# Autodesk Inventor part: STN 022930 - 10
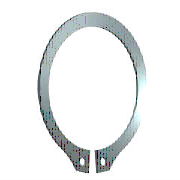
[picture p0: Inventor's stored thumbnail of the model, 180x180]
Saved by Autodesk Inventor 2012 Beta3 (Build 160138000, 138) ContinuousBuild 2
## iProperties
Created: 2010-02
Part Number: STN 022930 - 10
Material: Steel, Mild
Description: Retaining rings for shaft
Document SubType Name: Modeling
Standard: STN 022930
Designer: Thom Tremblay
Standards Organization: STN
Language: en-US
Size Designation: 10
Categories: <MemberInstance><Categories><Category DisplayName="Shaft Parts" InternalName="7f7aeb1f-a693-4053-b835-cee3144e0d98" Mnemonic="SHFT"><Category DisplayName="Circl
Density: 7.86 g/cm^3
IsCustomPart: 0
Author: Thom Tremblay
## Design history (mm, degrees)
node "WorkPlane1"
workplane "Work Plane2"
node "WorkPlane2"
node "Sketch1"
node "WorkPoint1"
node "WorkAxis1"
sketch "Sketch3"
  geometry: L1 (-0.75, -4.741)-(-0.75, -7.741) reference; L2 (-0.75, -7.741)-(-3.75, -7.212) reference; 1 further point
  dimensions: "d30" = 1.2 distance from line of L1 point (-1.95, -6.159) (= 0.8 x Diam5); "d32" = 1.35 distance from line of L2 point (-1.95, -6.159) (= 0.45 x ParA)
hole "Hole1" sketch "Sketch3" at (-1.95, -6.159) diameter "d33" = 1.5 (= Diam5); stored, may be unused: countersink angle "d37" = 60 deg, drill point angle "d39" = 118 deg; dims "d34" = 6, "d35" = 4, "d36" = 2, "d38" = 8
sketch "Sketch4"
  geometry: L1 (0.75, -7.741)-(0.75, -4.741) reference; L2 (3.75, -7.212)-(0.75, -7.741) reference; 1 further point
  dimensions: "d41" = 1.2 distance from line of L1 point (1.95, -6.159) (= 0.8 x Diam5); "d43" = 1.35 distance from line of L2 point (1.95, -6.159) (= 0.45 x ParA)
hole "Hole2" sketch "Sketch4" at (1.95, -6.159) diameter "d44" = 1.5 (= Diam5); stored, may be unused: countersink angle "d48" = 60 deg, drill point angle "d50" = 118 deg; dims "d45" = 6, "d46" = 4, "d47" = 2, "d49" = 8
fillet "Fillet1" dims "d51" = 2.25 (= 1.5 x Diam5)
body "Solid1"
sketch "Sketch2"
  geometry: L1 (3.75, -7.212)-(3.75, -4.537); L2 (0.75, -7.741)-(3.75, -7.212); L3 (0.75, -4.741)-(0.75, -7.741); L4 (-0.75, -4.741)-(-0.75, -7.741); L5 (-0.75, -7.741)-(-3.75, -7.212); L6 (-3.75, -7.212)-(-3.75, -4.537); A1 r 4.8 centre (0, 0) between (0.75, -4.741) and (-0.75, -4.741); A2 r 6.2 centre (0, 0.4) between (3.75, -4.537) and (-3.75, -4.537); 1 further point
  constraints: 12 end point, 4 point on circle, 4 vertical, 2 centre point
  dimensions: "d2" = 4.8 radius of A1 (= 0.5 x Diam2); "d4" = 6.2 radius of A2 (= 0.166667 x ParA + 0.5 x Diam2 + 0.5 x b); "d6" = 0 horizontal distance of A2.centre A1.centre; "d8" = 0.75 horizontal distance of L3.start A1.centre (= 0.5 x Diam5); "d10" = 0.75 horizontal distance of L4.start A1.centre (= 0.5 x Diam5); "d12" = 3 distance of L4.start L4.end (= ParA); "d14" = 3 distance of L3.start L2.start (= ParA); "d16" = 80 deg angle of L2 L3; "d18" = 80 deg angle of L4 L5; "d20" = 3 horizontal distance of L4.start L6.end (= 2 x Diam5); "d22" = 3 horizontal distance of L1.start L3.start (= 2 x Diam5); "d24" = 0.4 distance of A1.centre A2.centre (= -msp_r2 + 0.5 x Diam2 + b); "d52" = 0 distance of point (0, 0) A1.centre; "d53" = 0 distance of A1.centre point (0, 0)
extrude "Extrusion1" new body sketch "Sketch2" distance "d25" = 1 (= ParS); taper "d26" = 0 deg
other parameters: "Diam5" = 1.5 [user parameter; used in 9 equation terms], "ParA" = 3 [user parameter; used in 6 equation terms], "b" = 1.8 [user parameter; used in 3 equation terms], "ParS" = 1 [user parameter; used in 2 equation terms], "Diam2" = 9.6 [user parameter; used in 4 equation terms], "msp_r2" = 6.2 (= 0.166667 x ParA + 0.5 x Diam2 + 0.5 x b) [user parameter; used in 1 equation term], "d0" = -1 (computed from ParS), "d1" = 14.3 (derived), "d3" = 0, "d5" = 0 (derived), "d7" = 1 (derived), "d9" = 1 (derived), "d11" = 4.8 (derived), "d13" = 4.8 (derived), "d15" = 80 deg (derived), "d17" = 80 deg (derived), "d19" = 4 (derived), "d21" = 4 (derived), "d23" = 0.95 (derived), "d27" = 0, "d28" = 0, "d29" = 1.6 (derived), "d31" = 2.16 (derived), "d40" = 1.6 (derived), "d42" = 2.16 (derived), "d55" = 0, "d56" = 0, "d57" = 0, "d58" = 0, "TEMPLATE" = 12.345 [user parameter]
